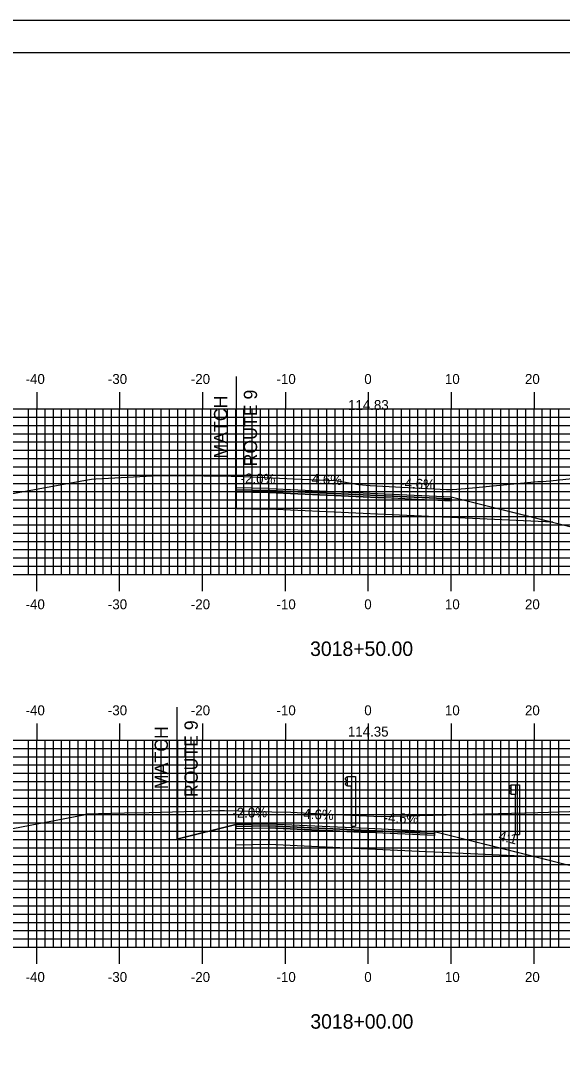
# Model space of a CAD drawing. Extents: x 1685586 to 1685929, y 461260 to 461480.
# Drawn here: x 1685709.8 to 1685775.2, y 461356.1 to 461480 of the extents above; entities that cross this region are included whole.
import ezdxf

# ---------------------------------------------------------------- set-up
doc = ezdxf.new("R2010")
doc.units = 0
for name, color, linetype in [('ANNOTATION', 7, 'Continuous'), ('BORDER', 7, 'Continuous'), ('D_Roadway_Centerline', 7, 'Continuous'), ('D_Roadway_Centerline_Text', 7, 'Continuous'), ('D_Roadway_Edge_Shoulder', 7, 'Continuous'), ('D_Roadway_Edge_TW', 7, 'Continuous'), ('D_Roadway_Pavement', 7, 'Continuous'), ('D_Roadway_SlopeLines', 7, 'Continuous'), ('D_Roadway_SubGrade', 7, 'Continuous'), ('H_V ANNOTATION', 7, 'Continuous'), ('M_Guardrail', 7, 'Continuous'), ('M_Roadway_Centerline', 7, 'Continuous'), ('MAJOR', 7, 'Continuous'), ('MINOR', 7, 'Continuous'), ('PLOT BOUNDARY', 7, 'Continuous'), ('S_Roadway_Centerline', 7, 'Continuous')]:
    doc.layers.add(name, color=color, linetype=linetype)

msp = doc.modelspace()

# ---------------------------------------------------------------- linework, layer by layer
at = {"layer": 'BORDER'}
msp.add_lwpolyline([(1685602.14, 461266.07), (1685922.14, 461266.07), (1685922.14, 461476.07), (1685602.14, 461476.07)], close=True, dxfattribs=at)
at = {"layer": 'D_Roadway_Centerline'}
msp.add_lwpolyline([(1685728.63, 461381.11), (1685735.74, 461382.89), (1685739.74, 461382.97), (1685751.74, 461382.42), (1685759.74, 461382.05), (1685772, 461378.99), (1685776, 461377.99), (1685843.58, 461379.3)], dxfattribs=at)
at = {"layer": 'D_Roadway_Edge_Shoulder'}
for points in [[(1685739.74, 461423.45), (1685735.79, 461423.53), (1685735.79, 461423.28), (1685739.74, 461423.2)], [(1685753.74, 461422.81), (1685761.74, 461422.44), (1685761.74, 461422.19), (1685753.74, 461422.56)], [(1685753.74, 461422.56), (1685761.74, 461422.19), (1685761.74, 461421.94), (1685753.74, 461422.31)], [(1685739.74, 461382.97), (1685735.74, 461382.89), (1685735.74, 461382.64), (1685739.74, 461382.72)], [(1685739.74, 461382.72), (1685735.74, 461382.64), (1685735.74, 461382.39), (1685739.74, 461382.47)], [(1685751.74, 461382.42), (1685759.74, 461382.05), (1685759.74, 461381.8), (1685751.74, 461382.17)], [(1685751.74, 461382.17), (1685759.74, 461381.8), (1685759.74, 461381.55), (1685751.74, 461381.92)]]:
    msp.add_lwpolyline(points, close=True, dxfattribs=at)
at = {"layer": 'D_Roadway_Edge_TW'}
for points in [[(1685739.74, 461423.45), (1685753.74, 461422.81), (1685753.74, 461422.56), (1685739.74, 461423.2)], [(1685739.74, 461423.45), (1685753.74, 461422.81), (1685753.74, 461422.56), (1685739.74, 461423.2)], [(1685739.74, 461423.45), (1685753.74, 461422.81), (1685753.74, 461422.56), (1685739.74, 461423.2)], [(1685739.74, 461382.97), (1685751.74, 461382.42), (1685751.74, 461382.17), (1685739.74, 461382.72)]]:
    msp.add_lwpolyline(points, close=True, dxfattribs=at)
for points in [[(1685739.74, 461423.45), (1685739.74, 461423.2)], [(1685753.74, 461422.56), (1685753.74, 461422.81)]]:
    msp.add_lwpolyline(points, dxfattribs=at)
at = {"layer": 'D_Roadway_Pavement'}
for points in [[(1685739.74, 461423.2), (1685735.79, 461423.28), (1685735.79, 461423.03), (1685739.74, 461422.95)], [(1685739.74, 461423.2), (1685753.74, 461422.56), (1685753.74, 461422.31), (1685739.74, 461422.95)], [(1685739.74, 461423.2), (1685753.74, 461422.56), (1685753.74, 461422.31), (1685739.74, 461422.95)], [(1685739.74, 461423.2), (1685753.74, 461422.56), (1685753.74, 461422.31), (1685739.74, 461422.95)], [(1685739.74, 461423.2), (1685753.74, 461422.56), (1685753.74, 461422.31), (1685739.74, 461422.95)], [(1685739.74, 461423.2), (1685753.74, 461422.56), (1685753.74, 461422.31), (1685739.74, 461422.95)], [(1685739.74, 461382.72), (1685751.74, 461382.17), (1685751.74, 461381.92), (1685739.74, 461382.47)]]:
    msp.add_lwpolyline(points, close=True, dxfattribs=at)
for points in [[(1685739.74, 461423.2), (1685739.74, 461422.95)], [(1685753.74, 461422.56), (1685753.74, 461422.31)], [(1685753.74, 461422.56), (1685753.74, 461422.31)], [(1685753.74, 461422.56), (1685753.74, 461422.31)], [(1685753.74, 461422.56), (1685753.74, 461422.31)], [(1685753.74, 461422.56), (1685753.74, 461422.31)], [(1685753.74, 461422.56), (1685753.74, 461422.31)], [(1685753.74, 461422.31), (1685753.74, 461422.56)], [(1685753.74, 461422.56), (1685753.74, 461422.31)], [(1685739.74, 461382.72), (1685739.74, 461382.47)], [(1685739.74, 461382.72), (1685739.74, 461382.47)], [(1685751.74, 461382.17), (1685751.74, 461381.92)], [(1685751.74, 461382.17), (1685751.74, 461381.92)], [(1685751.74, 461382.17), (1685751.74, 461381.92)]]:
    msp.add_lwpolyline(points, dxfattribs=at)
at = {"layer": 'D_Roadway_SlopeLines'}
for points in [[(1685761.74, 461422.44), (1685778, 461418.37)], [(1685735.74, 461382.89), (1685728.63, 461381.11)], [(1685759.74, 461382.05), (1685776, 461377.99)]]:
    msp.add_lwpolyline(points, dxfattribs=at)
at = {"layer": 'D_Roadway_SubGrade'}
for p, q in [((1685735.79, 461436.98), (1685735.79, 461421.03)), ((1685728.63, 461397.06), (1685728.63, 461381.11))]:
    msp.add_line(p, q, dxfattribs=at)
for points in [[(1685739.74, 461422.95), (1685735.79, 461423.03), (1685735.79, 461423.28), (1685735.79, 461421.03), (1685739.74, 461420.95)], [(1685739.74, 461422.95), (1685753.74, 461422.31), (1685753.74, 461420.31), (1685739.74, 461420.95)], [(1685739.74, 461422.95), (1685753.74, 461422.31), (1685753.74, 461420.31), (1685739.74, 461420.95)], [(1685739.74, 461422.95), (1685753.74, 461422.31), (1685753.74, 461420.31), (1685739.74, 461420.95)], [(1685753.74, 461422.31), (1685753.74, 461422.56), (1685761.74, 461422.19), (1685761.74, 461422.44), (1685774, 461419.37), (1685753.74, 461420.31)], [(1685739.74, 461380.47), (1685735.74, 461380.39), (1685735.74, 461382.89), (1685735.74, 461382.64), (1685739.74, 461382.72), (1685739.74, 461382.47)], [(1685739.74, 461382.47), (1685751.74, 461381.92), (1685751.74, 461379.92), (1685739.74, 461380.47)], [(1685751.74, 461381.92), (1685751.74, 461382.17), (1685759.74, 461381.8), (1685759.74, 461382.05), (1685772, 461378.99), (1685751.74, 461379.92)]]:
    msp.add_lwpolyline(points, close=True, dxfattribs=at)
msp.add_lwpolyline([(1685739.74, 461422.95), (1685739.74, 461420.95)], dxfattribs=at)
msp.add_lwpolyline([(1685739.74, 461422.95), (1685739.74, 461420.95)], dxfattribs=at)
at = {"layer": 'M_Guardrail'}
for p, q in [((1685749.12, 461388.58), (1685748.98, 461388.48)), ((1685748.98, 461388.33), (1685749.17, 461388.2)), ((1685749.17, 461387.98), (1685748.98, 461387.84)), ((1685749.22, 461388.6), (1685749.14, 461388.58)), ((1685749.21, 461388.13), (1685749.21, 461388.04)), ((1685749.22, 461388.67), (1685749.71, 461388.67)), ((1685749.22, 461387.5), (1685749.22, 461388.67)), ((1685749.71, 461388.67), (1685750.2, 461388.67)), ((1685749.71, 461388.67), (1685749.71, 461387.5)), ((1685750.2, 461388.67), (1685750.2, 461382.67)), ((1685748.98, 461387.7), (1685749.12, 461387.6)), ((1685749.14, 461387.59), (1685749.22, 461387.58)), ((1685749.71, 461387.5), (1685749.22, 461387.5)), ((1685749.71, 461382.67), (1685749.71, 461387.5)), ((1685768.9, 461387.59), (1685768.76, 461387.49)), ((1685768.76, 461387.35), (1685768.95, 461387.21)), ((1685768.95, 461386.99), (1685768.76, 461386.86)), ((1685768.76, 461386.71), (1685768.9, 461386.61)), ((1685769, 461387.61), (1685768.92, 461387.6)), ((1685768.92, 461386.61), (1685769, 461386.59)), ((1685768.99, 461387.15), (1685768.99, 461387.06)), ((1685769, 461387.69), (1685769.49, 461387.69)), ((1685769, 461386.52), (1685769, 461387.69)), ((1685769.49, 461387.69), (1685769.98, 461387.69)), ((1685769.49, 461387.69), (1685769.49, 461386.52)), ((1685769.98, 461387.69), (1685769.98, 461381.69)), ((1685769.49, 461386.52), (1685769, 461386.52)), ((1685769.49, 461381.69), (1685769.49, 461386.52)), ((1685749.71, 461382.67), (1685750.2, 461382.67)), ((1685769.49, 461381.69), (1685769.98, 461381.69))]:
    msp.add_line(p, q, dxfattribs=at)
for centre, major_axis, start_param, end_param in [((1685749.03, 461388.4), (-0.0877, 0), 5.323254, 7.243116), ((1685749.03, 461387.77), (-0.0877, 0), 5.323254, 7.243116), ((1685749.14, 461388.54), (-0.0417, 0), 4.886922, 5.323254), ((1685749.13, 461388.13), (0.0789, 0), 0, 0.959931), ((1685749.13, 461388.04), (0.0789, 0), 5.323254, 6.283185), ((1685749.14, 461387.63), (-0.0417, 0), 0.959931, 1.396263), ((1685768.81, 461387.42), (-0.0877, 0), 5.323254, 7.243116), ((1685768.81, 461386.79), (-0.0877, 0), 5.323254, 7.243116), ((1685768.93, 461387.56), (-0.0417, 0), 4.886922, 5.323254), ((1685768.93, 461386.65), (-0.0417, 0), 0.959931, 1.396263), ((1685768.91, 461387.15), (0.0789, 0), 0, 0.959931), ((1685768.91, 461387.06), (0.0789, 0), 5.323254, 6.283185)]:
    msp.add_ellipse(centre, major_axis=major_axis, ratio=0.995501, start_param=start_param, end_param=end_param, dxfattribs=at)
at = {"layer": 'MAJOR'}
for p, q in [((1685711.74, 461435.08), (1685711.74, 461433.07)), ((1685721.74, 461435.08), (1685721.74, 461433.07)), ((1685731.74, 461435.08), (1685731.74, 461433.07)), ((1685741.74, 461435.08), (1685741.74, 461433.07)), ((1685751.74, 461435.08), (1685751.74, 461433.07)), ((1685761.74, 461435.08), (1685761.74, 461433.07)), ((1685771.74, 461435.08), (1685771.74, 461433.07)), ((1685611.74, 461433.07), (1685891.74, 461433.07)), ((1685611.74, 461433.07), (1685891.74, 461433.07)), ((1685711.74, 461413.07), (1685711.74, 461433.07)), ((1685721.74, 461413.07), (1685721.74, 461433.07)), ((1685731.74, 461413.07), (1685731.74, 461433.07)), ((1685741.74, 461413.07), (1685741.74, 461433.07)), ((1685751.74, 461413.07), (1685751.74, 461433.07)), ((1685761.74, 461413.07), (1685761.74, 461433.07)), ((1685771.74, 461413.07), (1685771.74, 461433.07)), ((1685611.74, 461428.07), (1685891.74, 461428.07)), ((1685611.74, 461423.07), (1685891.74, 461423.07)), ((1685611.74, 461418.07), (1685891.74, 461418.07)), ((1685611.74, 461413.07), (1685891.74, 461413.07)), ((1685611.74, 461413.07), (1685891.74, 461413.07)), ((1685711.74, 461411.07), (1685711.74, 461413.07)), ((1685721.74, 461411.07), (1685721.74, 461413.07)), ((1685731.74, 461411.07), (1685731.74, 461413.07)), ((1685741.74, 461411.07), (1685741.74, 461413.07)), ((1685751.74, 461411.07), (1685751.74, 461413.07)), ((1685761.74, 461411.07), (1685761.74, 461413.07)), ((1685771.74, 461411.07), (1685771.74, 461413.07)), ((1685711.74, 461395.08), (1685711.74, 461393.07)), ((1685721.74, 461395.08), (1685721.74, 461393.07)), ((1685731.74, 461395.08), (1685731.74, 461393.07)), ((1685741.74, 461395.08), (1685741.74, 461393.07)), ((1685751.74, 461395.08), (1685751.74, 461393.07)), ((1685761.74, 461395.08), (1685761.74, 461393.07)), ((1685771.74, 461395.08), (1685771.74, 461393.07)), ((1685611.74, 461393.07), (1685891.74, 461393.07)), ((1685611.74, 461393.07), (1685891.74, 461393.07)), ((1685711.74, 461368.07), (1685711.74, 461393.07)), ((1685721.74, 461368.07), (1685721.74, 461393.07)), ((1685731.74, 461368.07), (1685731.74, 461393.07)), ((1685741.74, 461368.07), (1685741.74, 461393.07)), ((1685751.74, 461368.07), (1685751.74, 461393.07)), ((1685761.74, 461368.07), (1685761.74, 461393.07)), ((1685771.74, 461368.07), (1685771.74, 461393.07)), ((1685611.74, 461388.07), (1685891.74, 461388.07)), ((1685611.74, 461383.07), (1685891.74, 461383.07)), ((1685611.74, 461378.07), (1685891.74, 461378.07)), ((1685611.74, 461373.07), (1685891.74, 461373.07)), ((1685611.74, 461368.07), (1685891.74, 461368.07)), ((1685611.74, 461368.07), (1685891.74, 461368.07)), ((1685711.74, 461366.07), (1685711.74, 461368.07)), ((1685721.74, 461366.07), (1685721.74, 461368.07)), ((1685731.74, 461366.07), (1685731.74, 461368.07)), ((1685741.74, 461366.07), (1685741.74, 461368.07)), ((1685751.74, 461366.07), (1685751.74, 461368.07)), ((1685761.74, 461366.07), (1685761.74, 461368.07)), ((1685771.74, 461366.07), (1685771.74, 461368.07))]:
    msp.add_line(p, q, dxfattribs=at)
at = {"layer": 'MINOR'}
for p, q in [((1685710.74, 461413.07), (1685710.74, 461433.07)), ((1685712.74, 461413.07), (1685712.74, 461433.07)), ((1685713.74, 461413.07), (1685713.74, 461433.07)), ((1685714.74, 461413.07), (1685714.74, 461433.07)), ((1685715.74, 461413.07), (1685715.74, 461433.07)), ((1685716.74, 461413.07), (1685716.74, 461433.07)), ((1685717.74, 461413.07), (1685717.74, 461433.07)), ((1685718.74, 461413.07), (1685718.74, 461433.07)), ((1685719.74, 461413.07), (1685719.74, 461433.07)), ((1685720.74, 461413.07), (1685720.74, 461433.07)), ((1685722.74, 461413.07), (1685722.74, 461433.07)), ((1685723.74, 461413.07), (1685723.74, 461433.07)), ((1685724.74, 461413.07), (1685724.74, 461433.07)), ((1685725.74, 461413.07), (1685725.74, 461433.07)), ((1685726.74, 461413.07), (1685726.74, 461433.07)), ((1685727.74, 461413.07), (1685727.74, 461433.07)), ((1685728.74, 461413.07), (1685728.74, 461433.07)), ((1685729.74, 461413.07), (1685729.74, 461433.07)), ((1685730.74, 461413.07), (1685730.74, 461433.07)), ((1685732.74, 461413.07), (1685732.74, 461433.07)), ((1685733.74, 461413.07), (1685733.74, 461433.07)), ((1685734.74, 461413.07), (1685734.74, 461433.07)), ((1685735.74, 461413.07), (1685735.74, 461433.07)), ((1685736.74, 461413.07), (1685736.74, 461433.07)), ((1685737.74, 461413.07), (1685737.74, 461433.07)), ((1685738.74, 461413.07), (1685738.74, 461433.07)), ((1685739.74, 461413.07), (1685739.74, 461433.07)), ((1685740.74, 461413.07), (1685740.74, 461433.07)), ((1685742.74, 461413.07), (1685742.74, 461433.07)), ((1685743.74, 461413.07), (1685743.74, 461433.07)), ((1685744.74, 461413.07), (1685744.74, 461433.07)), ((1685745.74, 461413.07), (1685745.74, 461433.07)), ((1685746.74, 461413.07), (1685746.74, 461433.07)), ((1685747.74, 461413.07), (1685747.74, 461433.07)), ((1685748.74, 461413.07), (1685748.74, 461433.07)), ((1685749.74, 461413.07), (1685749.74, 461433.07)), ((1685750.74, 461413.07), (1685750.74, 461433.07)), ((1685752.74, 461413.07), (1685752.74, 461433.07)), ((1685753.74, 461413.07), (1685753.74, 461433.07)), ((1685754.74, 461413.07), (1685754.74, 461433.07)), ((1685755.74, 461413.07), (1685755.74, 461433.07)), ((1685756.74, 461413.07), (1685756.74, 461433.07)), ((1685757.74, 461413.07), (1685757.74, 461433.07)), ((1685758.74, 461413.07), (1685758.74, 461433.07)), ((1685759.74, 461413.07), (1685759.74, 461433.07)), ((1685760.74, 461413.07), (1685760.74, 461433.07)), ((1685762.74, 461413.07), (1685762.74, 461433.07)), ((1685763.74, 461413.07), (1685763.74, 461433.07)), ((1685764.74, 461413.07), (1685764.74, 461433.07)), ((1685765.74, 461413.07), (1685765.74, 461433.07)), ((1685766.74, 461413.07), (1685766.74, 461433.07)), ((1685767.74, 461413.07), (1685767.74, 461433.07)), ((1685768.74, 461413.07), (1685768.74, 461433.07)), ((1685769.74, 461413.07), (1685769.74, 461433.07)), ((1685770.74, 461413.07), (1685770.74, 461433.07)), ((1685772.74, 461413.07), (1685772.74, 461433.07)), ((1685773.74, 461413.07), (1685773.74, 461433.07)), ((1685774.74, 461413.07), (1685774.74, 461433.07)), ((1685611.74, 461432.07), (1685891.74, 461432.07)), ((1685611.74, 461431.07), (1685891.74, 461431.07)), ((1685611.74, 461430.07), (1685891.74, 461430.07)), ((1685611.74, 461429.07), (1685891.74, 461429.07)), ((1685611.74, 461427.07), (1685891.74, 461427.07)), ((1685611.74, 461426.07), (1685891.74, 461426.07)), ((1685611.74, 461425.07), (1685891.74, 461425.07)), ((1685611.74, 461424.07), (1685891.74, 461424.07)), ((1685611.74, 461422.07), (1685891.74, 461422.07)), ((1685611.74, 461421.07), (1685891.74, 461421.07)), ((1685611.74, 461420.07), (1685891.74, 461420.07)), ((1685611.74, 461419.07), (1685891.74, 461419.07)), ((1685611.74, 461417.07), (1685891.74, 461417.07)), ((1685611.74, 461416.07), (1685891.74, 461416.07)), ((1685611.74, 461415.07), (1685891.74, 461415.07)), ((1685611.74, 461414.07), (1685891.74, 461414.07)), ((1685710.74, 461368.07), (1685710.74, 461393.07)), ((1685712.74, 461368.07), (1685712.74, 461393.07)), ((1685713.74, 461368.07), (1685713.74, 461393.07)), ((1685714.74, 461368.07), (1685714.74, 461393.07)), ((1685715.74, 461368.07), (1685715.74, 461393.07)), ((1685716.74, 461368.07), (1685716.74, 461393.07)), ((1685717.74, 461368.07), (1685717.74, 461393.07)), ((1685718.74, 461368.07), (1685718.74, 461393.07)), ((1685719.74, 461368.07), (1685719.74, 461393.07)), ((1685720.74, 461368.07), (1685720.74, 461393.07)), ((1685722.74, 461368.07), (1685722.74, 461393.07)), ((1685723.74, 461368.07), (1685723.74, 461393.07)), ((1685724.74, 461368.07), (1685724.74, 461393.07)), ((1685725.74, 461368.07), (1685725.74, 461393.07)), ((1685726.74, 461368.07), (1685726.74, 461393.07)), ((1685727.74, 461368.07), (1685727.74, 461393.07)), ((1685728.74, 461368.07), (1685728.74, 461393.07)), ((1685729.74, 461368.07), (1685729.74, 461393.07)), ((1685730.74, 461368.07), (1685730.74, 461393.07)), ((1685732.74, 461368.07), (1685732.74, 461393.07)), ((1685733.74, 461368.07), (1685733.74, 461393.07)), ((1685734.74, 461368.07), (1685734.74, 461393.07)), ((1685735.74, 461368.07), (1685735.74, 461393.07)), ((1685736.74, 461368.07), (1685736.74, 461393.07)), ((1685737.74, 461368.07), (1685737.74, 461393.07)), ((1685738.74, 461368.07), (1685738.74, 461393.07)), ((1685739.74, 461368.07), (1685739.74, 461393.07)), ((1685740.74, 461368.07), (1685740.74, 461393.07)), ((1685742.74, 461368.07), (1685742.74, 461393.07)), ((1685743.74, 461368.07), (1685743.74, 461393.07)), ((1685744.74, 461368.07), (1685744.74, 461393.07)), ((1685745.74, 461368.07), (1685745.74, 461393.07)), ((1685746.74, 461368.07), (1685746.74, 461393.07)), ((1685747.74, 461368.07), (1685747.74, 461393.07)), ((1685748.74, 461368.07), (1685748.74, 461393.07)), ((1685749.74, 461368.07), (1685749.74, 461393.07)), ((1685750.74, 461368.07), (1685750.74, 461393.07)), ((1685752.74, 461368.07), (1685752.74, 461393.07)), ((1685753.74, 461368.07), (1685753.74, 461393.07)), ((1685754.74, 461368.07), (1685754.74, 461393.07)), ((1685755.74, 461368.07), (1685755.74, 461393.07)), ((1685756.74, 461368.07), (1685756.74, 461393.07)), ((1685757.74, 461368.07), (1685757.74, 461393.07)), ((1685758.74, 461368.07), (1685758.74, 461393.07)), ((1685759.74, 461368.07), (1685759.74, 461393.07)), ((1685760.74, 461368.07), (1685760.74, 461393.07)), ((1685762.74, 461368.07), (1685762.74, 461393.07)), ((1685763.74, 461368.07), (1685763.74, 461393.07)), ((1685764.74, 461368.07), (1685764.74, 461393.07)), ((1685765.74, 461368.07), (1685765.74, 461393.07)), ((1685766.74, 461368.07), (1685766.74, 461393.07)), ((1685767.74, 461368.07), (1685767.74, 461393.07)), ((1685768.74, 461368.07), (1685768.74, 461393.07)), ((1685769.74, 461368.07), (1685769.74, 461393.07)), ((1685770.74, 461368.07), (1685770.74, 461393.07)), ((1685772.74, 461368.07), (1685772.74, 461393.07)), ((1685773.74, 461368.07), (1685773.74, 461393.07)), ((1685774.74, 461368.07), (1685774.74, 461393.07)), ((1685611.74, 461392.07), (1685891.74, 461392.07)), ((1685611.74, 461391.07), (1685891.74, 461391.07)), ((1685611.74, 461390.07), (1685891.74, 461390.07)), ((1685611.74, 461389.07), (1685891.74, 461389.07)), ((1685611.74, 461387.07), (1685891.74, 461387.07)), ((1685611.74, 461386.07), (1685891.74, 461386.07)), ((1685611.74, 461385.07), (1685891.74, 461385.07)), ((1685611.74, 461384.07), (1685891.74, 461384.07)), ((1685611.74, 461382.07), (1685891.74, 461382.07)), ((1685611.74, 461381.07), (1685891.74, 461381.07)), ((1685611.74, 461380.07), (1685891.74, 461380.07)), ((1685611.74, 461379.07), (1685891.74, 461379.07)), ((1685611.74, 461377.07), (1685891.74, 461377.07)), ((1685611.74, 461376.07), (1685891.74, 461376.07)), ((1685611.74, 461375.07), (1685891.74, 461375.07)), ((1685611.74, 461374.07), (1685891.74, 461374.07)), ((1685611.74, 461372.07), (1685891.74, 461372.07)), ((1685611.74, 461371.07), (1685891.74, 461371.07)), ((1685611.74, 461370.07), (1685891.74, 461370.07)), ((1685611.74, 461369.07), (1685891.74, 461369.07))]:
    msp.add_line(p, q, dxfattribs=at)
at = {"layer": 'PLOT BOUNDARY'}
msp.add_lwpolyline([(1685585.96, 461259.95), (1685925.96, 461259.95), (1685925.96, 461479.95), (1685585.96, 461479.95)], close=True, dxfattribs=at)
at = {"layer": 'S_Roadway_Centerline'}
for points in [[(1685706.16, 461422.36), (1685717.62, 461424.47), (1685718.35, 461424.57), (1685718.88, 461424.61), (1685726.47, 461425.04), (1685728.61, 461425.03), (1685735.2, 461424.95), (1685736.72, 461424.9), (1685742.75, 461424.63), (1685747.85, 461424.42), (1685750.57, 461423.95), (1685751.95, 461423.83), (1685761.17, 461423.34), (1685761.92, 461423.33), (1685763.46, 461423.45), (1685772.19, 461424.29), (1685772.81, 461424.31), (1685774.07, 461424.42), (1685777.5, 461424.76)], [(1685705.87, 461381.82), (1685710.94, 461382.8), (1685717.4, 461384.05), (1685717.77, 461384.18), (1685719.19, 461384.2), (1685722.32, 461384.31), (1685725.28, 461384.35), (1685733.78, 461384.58), (1685734.41, 461384.59), (1685736.08, 461384.54), (1685740.1, 461384.42), (1685742.39, 461384.36), (1685746.95, 461384.14), (1685753.34, 461383.86), (1685756.39, 461383.91), (1685772.21, 461384.35), (1685778.57, 461384.52)]]:
    msp.add_lwpolyline(points, dxfattribs=at)

# ---------------------------------------------------------------- texts
at = {"layer": 'ANNOTATION'}
for s, height, rotation, p in [('ROUTE 9', 1.6, 90, (1685738.32, 461426.11)), ('MATCH', 1.6, 90, (1685734.72, 461427.07)), ('-2.0%', 1.2, 358.8861, (1685736.33, 461424.08)), ('4.6%', 1.2, 357.3662, (1685744.89, 461424.02)), ('-4.6%', 1.2, 357.3663, (1685755.57, 461423.52)), ('ROUTE 9', 1.6, 90, (1685731.16, 461386.19)), ('MATCH', 1.6, 90, (1685727.56, 461387.15)), ('-2.0%', 1.2, 1.1458, (1685735.35, 461383.68)), ('4.6%', 1.2, 357.3663, (1685743.89, 461383.58)), ('-4.6%', 1.2, 357.3663, (1685753.57, 461383.14)), ('4:1', 1.2, 345.9638, (1685767.38, 461381))]:
    msp.add_text(s, height=height, rotation=rotation, dxfattribs=at).set_placement(p)
at = {"layer": 'D_Roadway_Centerline_Text'}
for s, p in [('114.83', (1685749.3, 461432.93)), ('114.35', (1685749.28, 461393.5))]:
    msp.add_text(s, height=1.2, dxfattribs=at).set_placement(p)
at = {"layer": 'H_V ANNOTATION'}
for s, height, p in [('-40', 1.2, (1685710.39, 461436.07)), ('-30', 1.2, (1685720.32, 461436.07)), ('-20', 1.2, (1685730.33, 461436.07)), ('-10', 1.2, (1685740.67, 461436.07)), ('0', 1.2, (1685751.26, 461436.07)), ('10', 1.2, (1685760.99, 461436.07)), ('20', 1.2, (1685770.65, 461436.07)), ('-40', 1.2, (1685710.39, 461408.87)), ('-30', 1.2, (1685720.32, 461408.87)), ('-20', 1.2, (1685730.33, 461408.87)), ('-10', 1.2, (1685740.67, 461408.87)), ('0', 1.2, (1685751.26, 461408.87)), ('10', 1.2, (1685760.99, 461408.87)), ('20', 1.2, (1685770.65, 461408.87)), ('3018+50.00', 1.75, (1685744.72, 461403.23)), ('-40', 1.2, (1685710.39, 461396.07)), ('-30', 1.2, (1685720.32, 461396.07)), ('-20', 1.2, (1685730.33, 461396.07)), ('-10', 1.2, (1685740.67, 461396.07)), ('0', 1.2, (1685751.26, 461396.07)), ('10', 1.2, (1685760.99, 461396.07)), ('20', 1.2, (1685770.65, 461396.07)), ('-40', 1.2, (1685710.39, 461363.87)), ('-30', 1.2, (1685720.32, 461363.87)), ('-20', 1.2, (1685730.33, 461363.87)), ('-10', 1.2, (1685740.67, 461363.87)), ('0', 1.2, (1685751.26, 461363.87)), ('10', 1.2, (1685760.99, 461363.87)), ('20', 1.2, (1685770.65, 461363.87)), ('3018+00.00', 1.75, (1685744.75, 461358.23))]:
    msp.add_text(s, height=height, dxfattribs=at).set_placement(p)
at = {"layer": 'M_Roadway_Centerline'}
for s, p in [('C', (1685735.19, 461424.95)), ('L', (1685735.2, 461424.94)), ('C', (1685734.4, 461384.59)), ('L', (1685734.41, 461384.58))]:
    msp.add_text(s, height=0.0146, dxfattribs=at).set_placement(p)

doc.saveas('drawing.dxf')
